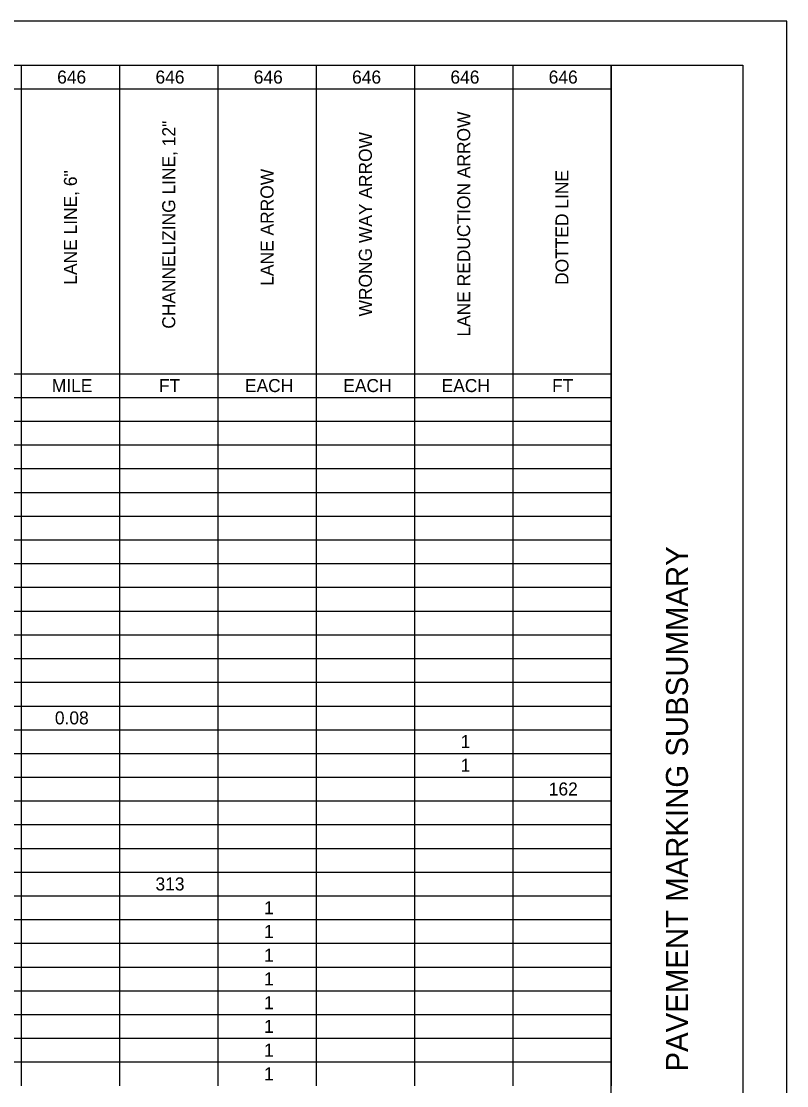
# Model space of a CAD drawing. Extents: x 0 to 34, y 0 to 22.
# Drawn here: x 25.28 to 34, y 9.88 to 22 of the extents above; entities that cross this region are included whole.
import ezdxf

# ---------------------------------------------------------------- set-up
doc = ezdxf.new("R2010")
doc.units = 0
for name, color, linetype in [('SH_Border', 7, 'Continuous'), ('SH_Cut_Line', 7, 'Continuous'), ('SH_Data', 7, 'Continuous')]:
    doc.layers.add(name, color=color, linetype=linetype)

msp = doc.modelspace()

# ---------------------------------------------------------------- linework, layer by layer
at = {"layer": 'SH_Border'}
msp.add_line((32, 0.5), (32, 21.5), dxfattribs=at)
msp.add_lwpolyline([(1.5, 21.5), (33.5, 21.5), (33.5, 0.5), (1.5, 0.5)], close=True, dxfattribs=at)
at = {"layer": 'SH_Cut_Line'}
msp.add_lwpolyline([(0, 0), (34, 0), (34, 22), (0, 22)], close=True, dxfattribs=at)
at = {"layer": 'SH_Data'}
for p, q in [((24.163, 21.5), (25.282, 21.5)), ((25.282, 21.5), (27.522, 21.5)), ((25.282, 21.5), (25.282, 21.23)), ((26.402, 21.5), (26.402, 21.23)), ((27.522, 21.5), (30.88, 21.5)), ((27.522, 21.5), (27.522, 21.23)), ((28.641, 21.5), (28.641, 21.23)), ((29.761, 21.5), (29.761, 21.23)), ((30.88, 21.5), (32, 21.5)), ((30.88, 21.5), (30.88, 21.23)), ((32, 21.5), (32, 21.23)), ((24.163, 21.23), (25.282, 21.23)), ((25.282, 21.23), (27.522, 21.23)), ((25.282, 21.23), (25.282, 20.96)), ((26.402, 21.23), (26.402, 20.96)), ((27.522, 21.23), (30.88, 21.23)), ((27.522, 21.23), (27.522, 20.96)), ((28.641, 21.23), (28.641, 20.96)), ((29.761, 21.23), (29.761, 20.96)), ((30.88, 21.23), (32, 21.23)), ((30.88, 21.23), (30.88, 20.96)), ((32, 21.23), (32, 20.96)), ((25.282, 20.96), (25.282, 20.69)), ((26.402, 20.96), (26.402, 20.69)), ((27.522, 20.96), (27.522, 20.69)), ((28.641, 20.96), (28.641, 20.69)), ((29.761, 20.96), (29.761, 20.69)), ((30.88, 20.96), (30.88, 20.69)), ((32, 20.96), (32, 20.69)), ((25.282, 20.69), (25.282, 20.419)), ((26.402, 20.69), (26.402, 20.419)), ((27.522, 20.69), (27.522, 20.419)), ((28.641, 20.69), (28.641, 20.419)), ((29.761, 20.69), (29.761, 20.419)), ((30.88, 20.69), (30.88, 20.419)), ((32, 20.69), (32, 20.419)), ((25.282, 20.419), (25.282, 20.149)), ((26.402, 20.419), (26.402, 20.149)), ((27.522, 20.419), (27.522, 20.149)), ((28.641, 20.419), (28.641, 20.149)), ((29.761, 20.419), (29.761, 20.149)), ((30.88, 20.419), (30.88, 20.149)), ((32, 20.419), (32, 20.149)), ((25.282, 20.149), (25.282, 19.879)), ((26.402, 20.149), (26.402, 19.879)), ((27.522, 20.149), (27.522, 19.879)), ((28.641, 20.149), (28.641, 19.879)), ((29.761, 20.149), (29.761, 19.879)), ((30.88, 20.149), (30.88, 19.879)), ((32, 20.149), (32, 19.879)), ((25.282, 19.879), (25.282, 19.609)), ((26.402, 19.879), (26.402, 19.609)), ((27.522, 19.879), (27.522, 19.609)), ((28.641, 19.879), (28.641, 19.609)), ((29.761, 19.879), (29.761, 19.609)), ((30.88, 19.879), (30.88, 19.609)), ((32, 19.879), (32, 19.609)), ((25.282, 19.609), (25.282, 19.338)), ((26.402, 19.609), (26.402, 19.338)), ((27.522, 19.609), (27.522, 19.338)), ((28.641, 19.609), (28.641, 19.338)), ((29.761, 19.609), (29.761, 19.338)), ((30.88, 19.609), (30.88, 19.338)), ((32, 19.609), (32, 19.338)), ((25.282, 19.338), (25.282, 19.068)), ((26.402, 19.338), (26.402, 19.068)), ((27.522, 19.338), (27.522, 19.068)), ((28.641, 19.338), (28.641, 19.068)), ((29.761, 19.338), (29.761, 19.068)), ((30.88, 19.338), (30.88, 19.068)), ((32, 19.338), (32, 19.068)), ((25.282, 19.068), (25.282, 18.798)), ((26.402, 19.068), (26.402, 18.798)), ((27.522, 19.068), (27.522, 18.798)), ((28.641, 19.068), (28.641, 18.798)), ((29.761, 19.068), (29.761, 18.798)), ((30.88, 19.068), (30.88, 18.798)), ((32, 19.068), (32, 18.798)), ((25.282, 18.798), (25.282, 18.528)), ((26.402, 18.798), (26.402, 18.528)), ((27.522, 18.798), (27.522, 18.528)), ((28.641, 18.798), (28.641, 18.528)), ((29.761, 18.798), (29.761, 18.528)), ((30.88, 18.798), (30.88, 18.528)), ((32, 18.798), (32, 18.528)), ((25.282, 18.528), (25.282, 18.257)), ((26.402, 18.528), (26.402, 18.257)), ((27.522, 18.528), (27.522, 18.257)), ((28.641, 18.528), (28.641, 18.257)), ((29.761, 18.528), (29.761, 18.257)), ((30.88, 18.528), (30.88, 18.257)), ((32, 18.528), (32, 18.257)), ((25.282, 18.257), (25.282, 17.987)), ((26.402, 18.257), (26.402, 17.987)), ((27.522, 18.257), (27.522, 17.987)), ((28.641, 18.257), (28.641, 17.987)), ((29.761, 18.257), (29.761, 17.987)), ((30.88, 18.257), (30.88, 17.987)), ((32, 18.257), (32, 17.987)), ((24.163, 17.987), (25.282, 17.987)), ((25.282, 17.987), (27.522, 17.987)), ((25.282, 17.987), (25.282, 17.717)), ((26.402, 17.987), (26.402, 17.717)), ((27.522, 17.987), (30.88, 17.987)), ((27.522, 17.987), (27.522, 17.717)), ((28.641, 17.987), (28.641, 17.717)), ((29.761, 17.987), (29.761, 17.717)), ((30.88, 17.987), (32, 17.987)), ((30.88, 17.987), (30.88, 17.717)), ((32, 17.987), (32, 17.717)), ((24.163, 17.717), (25.282, 17.717)), ((25.282, 17.717), (27.522, 17.717)), ((25.282, 17.717), (25.282, 17.447)), ((26.402, 17.717), (26.402, 17.447)), ((27.522, 17.717), (30.88, 17.717)), ((27.522, 17.717), (27.522, 17.447)), ((28.641, 17.717), (28.641, 17.447)), ((29.761, 17.717), (29.761, 17.447)), ((30.88, 17.717), (32, 17.717)), ((30.88, 17.717), (30.88, 17.447)), ((32, 17.717), (32, 17.447)), ((24.163, 17.447), (25.282, 17.447)), ((25.282, 17.447), (27.522, 17.447)), ((25.282, 17.447), (25.282, 17.176)), ((26.402, 17.447), (26.402, 17.176)), ((27.522, 17.447), (30.88, 17.447)), ((27.522, 17.447), (27.522, 17.176)), ((28.641, 17.447), (28.641, 17.176)), ((29.761, 17.447), (29.761, 17.176)), ((30.88, 17.447), (32, 17.447)), ((30.88, 17.447), (30.88, 17.176)), ((32, 17.447), (32, 17.176)), ((24.163, 17.176), (25.282, 17.176)), ((25.282, 17.176), (27.522, 17.176)), ((25.282, 17.176), (25.282, 16.906)), ((26.402, 17.176), (26.402, 16.906)), ((27.522, 17.176), (30.88, 17.176)), ((27.522, 17.176), (27.522, 16.906)), ((28.641, 17.176), (28.641, 16.906)), ((29.761, 17.176), (29.761, 16.906)), ((30.88, 17.176), (32, 17.176)), ((30.88, 17.176), (30.88, 16.906)), ((32, 17.176), (32, 16.906)), ((24.163, 16.906), (25.282, 16.906)), ((25.282, 16.906), (27.522, 16.906)), ((25.282, 16.906), (25.282, 16.636)), ((26.402, 16.906), (26.402, 16.636)), ((27.522, 16.906), (30.88, 16.906)), ((27.522, 16.906), (27.522, 16.636)), ((28.641, 16.906), (28.641, 16.636)), ((29.761, 16.906), (29.761, 16.636)), ((30.88, 16.906), (32, 16.906)), ((30.88, 16.906), (30.88, 16.636)), ((32, 16.906), (32, 16.636)), ((24.163, 16.636), (25.282, 16.636)), ((25.282, 16.636), (27.522, 16.636)), ((25.282, 16.636), (25.282, 16.365)), ((26.402, 16.636), (26.402, 16.365)), ((27.522, 16.636), (30.88, 16.636)), ((27.522, 16.636), (27.522, 16.365)), ((28.641, 16.636), (28.641, 16.365)), ((29.761, 16.636), (29.761, 16.365)), ((30.88, 16.636), (32, 16.636)), ((30.88, 16.636), (30.88, 16.365)), ((32, 16.636), (32, 16.365)), ((24.163, 16.365), (25.282, 16.365)), ((25.282, 16.365), (27.522, 16.365)), ((25.282, 16.365), (25.282, 16.095)), ((26.402, 16.365), (26.402, 16.095)), ((27.522, 16.365), (30.88, 16.365)), ((27.522, 16.365), (27.522, 16.095)), ((28.641, 16.365), (28.641, 16.095)), ((29.761, 16.365), (29.761, 16.095)), ((30.88, 16.365), (32, 16.365)), ((30.88, 16.365), (30.88, 16.095)), ((32, 16.365), (32, 16.095)), ((24.163, 16.095), (25.282, 16.095)), ((25.282, 16.095), (27.522, 16.095)), ((25.282, 16.095), (25.282, 15.825)), ((26.402, 16.095), (26.402, 15.825)), ((27.522, 16.095), (30.88, 16.095)), ((27.522, 16.095), (27.522, 15.825)), ((28.641, 16.095), (28.641, 15.825)), ((29.761, 16.095), (29.761, 15.825)), ((30.88, 16.095), (32, 16.095)), ((30.88, 16.095), (30.88, 15.825)), ((32, 16.095), (32, 15.825)), ((24.163, 15.825), (25.282, 15.825)), ((25.282, 15.825), (27.522, 15.825)), ((25.282, 15.825), (25.282, 15.555)), ((26.402, 15.825), (26.402, 15.555)), ((27.522, 15.825), (30.88, 15.825)), ((27.522, 15.825), (27.522, 15.555)), ((28.641, 15.825), (28.641, 15.555)), ((29.761, 15.825), (29.761, 15.555)), ((30.88, 15.825), (32, 15.825)), ((30.88, 15.825), (30.88, 15.555)), ((32, 15.825), (32, 15.555)), ((24.163, 15.555), (25.282, 15.555)), ((25.282, 15.555), (27.522, 15.555)), ((25.282, 15.555), (25.282, 15.284)), ((26.402, 15.555), (26.402, 15.284)), ((27.522, 15.555), (30.88, 15.555)), ((27.522, 15.555), (27.522, 15.284)), ((28.641, 15.555), (28.641, 15.284)), ((29.761, 15.555), (29.761, 15.284)), ((30.88, 15.555), (32, 15.555)), ((30.88, 15.555), (30.88, 15.284)), ((32, 15.555), (32, 15.284)), ((24.163, 15.284), (25.282, 15.284)), ((25.282, 15.284), (27.522, 15.284)), ((25.282, 15.284), (25.282, 15.014)), ((26.402, 15.284), (26.402, 15.014)), ((27.522, 15.284), (30.88, 15.284)), ((27.522, 15.284), (27.522, 15.014)), ((28.641, 15.284), (28.641, 15.014)), ((29.761, 15.284), (29.761, 15.014)), ((30.88, 15.284), (32, 15.284)), ((30.88, 15.284), (30.88, 15.014)), ((32, 15.284), (32, 15.014)), ((24.163, 15.014), (25.282, 15.014)), ((25.282, 15.014), (27.522, 15.014)), ((25.282, 15.014), (25.282, 14.744)), ((26.402, 15.014), (26.402, 14.744)), ((27.522, 15.014), (30.88, 15.014)), ((27.522, 15.014), (27.522, 14.744)), ((28.641, 15.014), (28.641, 14.744)), ((29.761, 15.014), (29.761, 14.744)), ((30.88, 15.014), (32, 15.014)), ((30.88, 15.014), (30.88, 14.744)), ((32, 15.014), (32, 14.744)), ((24.163, 14.744), (25.282, 14.744)), ((25.282, 14.744), (27.522, 14.744)), ((25.282, 14.744), (25.282, 14.474)), ((26.402, 14.744), (26.402, 14.474)), ((27.522, 14.744), (30.88, 14.744)), ((27.522, 14.744), (27.522, 14.474)), ((28.641, 14.744), (28.641, 14.474)), ((29.761, 14.744), (29.761, 14.474)), ((30.88, 14.744), (32, 14.744)), ((30.88, 14.744), (30.88, 14.474)), ((32, 14.744), (32, 14.474)), ((24.163, 14.474), (25.282, 14.474)), ((25.282, 14.474), (27.522, 14.474)), ((25.282, 14.474), (25.282, 14.203)), ((26.402, 14.474), (26.402, 14.203)), ((27.522, 14.474), (30.88, 14.474)), ((27.522, 14.474), (27.522, 14.203)), ((28.641, 14.474), (28.641, 14.203)), ((29.761, 14.474), (29.761, 14.203)), ((30.88, 14.474), (32, 14.474)), ((30.88, 14.474), (30.88, 14.203)), ((32, 14.474), (32, 14.203)), ((24.163, 14.203), (25.282, 14.203)), ((25.282, 14.203), (27.522, 14.203)), ((25.282, 14.203), (25.282, 13.933)), ((26.402, 14.203), (26.402, 13.933)), ((27.522, 14.203), (30.88, 14.203)), ((27.522, 14.203), (27.522, 13.933)), ((28.641, 14.203), (28.641, 13.933)), ((29.761, 14.203), (29.761, 13.933)), ((30.88, 14.203), (32, 14.203)), ((30.88, 14.203), (30.88, 13.933)), ((32, 14.203), (32, 13.933)), ((24.163, 13.933), (25.282, 13.933)), ((25.282, 13.933), (27.522, 13.933)), ((25.282, 13.933), (25.282, 13.663)), ((26.402, 13.933), (26.402, 13.663)), ((27.522, 13.933), (30.88, 13.933)), ((27.522, 13.933), (27.522, 13.663)), ((28.641, 13.933), (28.641, 13.663)), ((29.761, 13.933), (29.761, 13.663)), ((30.88, 13.933), (32, 13.933)), ((30.88, 13.933), (30.88, 13.663)), ((32, 13.933), (32, 13.663)), ((24.163, 13.663), (25.282, 13.663)), ((25.282, 13.663), (27.522, 13.663)), ((25.282, 13.663), (25.282, 13.393)), ((26.402, 13.663), (26.402, 13.393)), ((27.522, 13.663), (30.88, 13.663)), ((27.522, 13.663), (27.522, 13.393)), ((28.641, 13.663), (28.641, 13.393)), ((29.761, 13.663), (29.761, 13.393)), ((30.88, 13.663), (32, 13.663)), ((30.88, 13.663), (30.88, 13.393)), ((32, 13.663), (32, 13.393)), ((24.163, 13.393), (25.282, 13.393)), ((25.282, 13.393), (27.522, 13.393)), ((25.282, 13.393), (25.282, 13.122)), ((26.402, 13.393), (26.402, 13.122)), ((27.522, 13.393), (30.88, 13.393)), ((27.522, 13.393), (27.522, 13.122)), ((28.641, 13.393), (28.641, 13.122)), ((29.761, 13.393), (29.761, 13.122)), ((30.88, 13.393), (32, 13.393)), ((30.88, 13.393), (30.88, 13.122)), ((32, 13.393), (32, 13.122)), ((24.163, 13.122), (25.282, 13.122)), ((25.282, 13.122), (27.522, 13.122)), ((25.282, 13.122), (25.282, 12.852)), ((26.402, 13.122), (26.402, 12.852)), ((27.522, 13.122), (30.88, 13.122)), ((27.522, 13.122), (27.522, 12.852)), ((28.641, 13.122), (28.641, 12.852)), ((29.761, 13.122), (29.761, 12.852)), ((30.88, 13.122), (32, 13.122)), ((30.88, 13.122), (30.88, 12.852)), ((32, 13.122), (32, 12.852)), ((24.163, 12.852), (25.282, 12.852)), ((25.282, 12.852), (27.522, 12.852)), ((25.282, 12.852), (25.282, 12.582)), ((26.402, 12.852), (26.402, 12.582)), ((27.522, 12.852), (30.88, 12.852)), ((27.522, 12.852), (27.522, 12.582)), ((28.641, 12.852), (28.641, 12.582)), ((29.761, 12.852), (29.761, 12.582)), ((30.88, 12.852), (32, 12.852)), ((30.88, 12.852), (30.88, 12.582)), ((32, 12.852), (32, 12.582)), ((24.163, 12.582), (25.282, 12.582)), ((25.282, 12.582), (27.522, 12.582)), ((25.282, 12.582), (25.282, 12.312)), ((26.402, 12.582), (26.402, 12.312)), ((27.522, 12.582), (30.88, 12.582)), ((27.522, 12.582), (27.522, 12.312)), ((28.641, 12.582), (28.641, 12.312)), ((29.761, 12.582), (29.761, 12.312)), ((30.88, 12.582), (32, 12.582)), ((30.88, 12.582), (30.88, 12.312)), ((32, 12.582), (32, 12.312)), ((24.163, 12.312), (25.282, 12.312)), ((25.282, 12.312), (27.522, 12.312)), ((25.282, 12.312), (25.282, 12.041)), ((26.402, 12.312), (26.402, 12.041)), ((27.522, 12.312), (30.88, 12.312)), ((27.522, 12.312), (27.522, 12.041)), ((28.641, 12.312), (28.641, 12.041)), ((29.761, 12.312), (29.761, 12.041)), ((30.88, 12.312), (32, 12.312)), ((30.88, 12.312), (30.88, 12.041)), ((32, 12.312), (32, 12.041)), ((24.163, 12.041), (25.282, 12.041)), ((25.282, 12.041), (27.522, 12.041)), ((25.282, 12.041), (25.282, 11.771)), ((26.402, 12.041), (26.402, 11.771)), ((27.522, 12.041), (30.88, 12.041)), ((27.522, 12.041), (27.522, 11.771)), ((28.641, 12.041), (28.641, 11.771)), ((29.761, 12.041), (29.761, 11.771)), ((30.88, 12.041), (32, 12.041)), ((30.88, 12.041), (30.88, 11.771)), ((32, 12.041), (32, 11.771)), ((24.163, 11.771), (25.282, 11.771)), ((25.282, 11.771), (27.522, 11.771)), ((25.282, 11.771), (25.282, 11.501)), ((26.402, 11.771), (26.402, 11.501)), ((27.522, 11.771), (30.88, 11.771)), ((27.522, 11.771), (27.522, 11.501)), ((28.641, 11.771), (28.641, 11.501)), ((29.761, 11.771), (29.761, 11.501)), ((30.88, 11.771), (32, 11.771)), ((30.88, 11.771), (30.88, 11.501)), ((32, 11.771), (32, 11.501)), ((24.163, 11.501), (25.282, 11.501)), ((25.282, 11.501), (27.522, 11.501)), ((25.282, 11.501), (25.282, 11.231)), ((26.402, 11.501), (26.402, 11.231)), ((27.522, 11.501), (30.88, 11.501)), ((27.522, 11.501), (27.522, 11.231)), ((28.641, 11.501), (28.641, 11.231)), ((29.761, 11.501), (29.761, 11.231)), ((30.88, 11.501), (32, 11.501)), ((30.88, 11.501), (30.88, 11.231)), ((32, 11.501), (32, 11.231)), ((24.163, 11.231), (25.282, 11.231)), ((25.282, 11.231), (27.522, 11.231)), ((25.282, 11.231), (25.282, 10.96)), ((26.402, 11.231), (26.402, 10.96)), ((27.522, 11.231), (30.88, 11.231)), ((27.522, 11.231), (27.522, 10.96)), ((28.641, 11.231), (28.641, 10.96)), ((29.761, 11.231), (29.761, 10.96)), ((30.88, 11.231), (32, 11.231)), ((30.88, 11.231), (30.88, 10.96)), ((32, 11.231), (32, 10.96)), ((24.163, 10.96), (25.282, 10.96)), ((25.282, 10.96), (27.522, 10.96)), ((25.282, 10.96), (25.282, 10.69)), ((26.402, 10.96), (26.402, 10.69)), ((27.522, 10.96), (30.88, 10.96)), ((27.522, 10.96), (27.522, 10.69)), ((28.641, 10.96), (28.641, 10.69)), ((29.761, 10.96), (29.761, 10.69)), ((30.88, 10.96), (32, 10.96)), ((30.88, 10.96), (30.88, 10.69)), ((32, 10.96), (32, 10.69)), ((24.163, 10.69), (25.282, 10.69)), ((25.282, 10.69), (27.522, 10.69)), ((25.282, 10.69), (25.282, 10.42)), ((26.402, 10.69), (26.402, 10.42)), ((27.522, 10.69), (30.88, 10.69)), ((27.522, 10.69), (27.522, 10.42)), ((28.641, 10.69), (28.641, 10.42)), ((29.761, 10.69), (29.761, 10.42)), ((30.88, 10.69), (32, 10.69)), ((30.88, 10.69), (30.88, 10.42)), ((32, 10.69), (32, 10.42)), ((24.163, 10.42), (25.282, 10.42)), ((25.282, 10.42), (27.522, 10.42)), ((25.282, 10.42), (25.282, 10.15)), ((26.402, 10.42), (26.402, 10.15)), ((27.522, 10.42), (30.88, 10.42)), ((27.522, 10.42), (27.522, 10.15)), ((28.641, 10.42), (28.641, 10.15)), ((29.761, 10.42), (29.761, 10.15)), ((30.88, 10.42), (32, 10.42)), ((30.88, 10.42), (30.88, 10.15)), ((32, 10.42), (32, 10.15)), ((24.163, 10.15), (25.282, 10.15)), ((25.282, 10.15), (27.522, 10.15)), ((25.282, 10.15), (25.282, 9.879)), ((26.402, 10.15), (26.402, 9.879)), ((27.522, 10.15), (30.88, 10.15)), ((27.522, 10.15), (27.522, 9.879)), ((28.641, 10.15), (28.641, 9.879)), ((29.761, 10.15), (29.761, 9.879)), ((30.88, 10.15), (32, 10.15)), ((30.88, 10.15), (30.88, 9.879)), ((32, 10.15), (32, 9.879))]:
    msp.add_line(p, q, dxfattribs=at)

# ---------------------------------------------------------------- texts
for s, p in [('646', (25.691, 21.291)), ('646', (26.811, 21.291)), ('646', (27.93, 21.291)), ('646', (29.05, 21.291)), ('646', (30.17, 21.291)), ('646', (31.289, 21.291)), ('MILE', (25.63, 17.778)), ('FT', (26.85, 17.778)), ('EACH', (27.83, 17.778)), ('EACH', (28.95, 17.778)), ('EACH', (30.07, 17.778)), ('FT', (31.328, 17.778)), ('0.08', (25.665, 13.994)), ('1', (30.286, 13.724)), ('1', (30.286, 13.454)), ('162', (31.29, 13.184)), ('313', (26.811, 12.103)), ('1', (28.047, 11.832)), ('1', (28.047, 11.562)), ('1', (28.047, 11.292)), ('1', (28.047, 11.022)), ('1', (28.047, 10.751)), ('1', (28.047, 10.481)), ('1', (28.047, 10.211)), ('1', (28.047, 9.941))]:
    msp.add_text(s, height=0.148, dxfattribs=at).set_placement(p)
for s, height, p in [('LANE REDUCTION ARROW', 0.148, (30.395, 18.41)), ('CHANNELIZING LINE, 12"', 0.148, (27.036, 18.499)), ('WRONG WAY ARROW', 0.148, (29.275, 18.639)), ('LANE LINE, 6"', 0.148, (25.916, 19.001)), ('LANE ARROW', 0.148, (28.155, 18.989)), ('DOTTED LINE', 0.148, (31.514, 18.998)), ('PAVEMENT MARKING SUBSUMMARY', 0.25, (32.875, 10.041))]:
    msp.add_text(s, height=height, rotation=90, dxfattribs=at).set_placement(p)

doc.saveas('drawing.dxf')
